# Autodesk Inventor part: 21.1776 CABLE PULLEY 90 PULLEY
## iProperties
Created: 2007-05
Part Number: 21.1776 CABLE PULLEY 90 PULLEY
Material: Steel
Document SubType Name: Modeling
Designer: Andy Moles
Density: 7.85 g/cm^3
Author: Andy Moles
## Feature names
1. Revolution1
